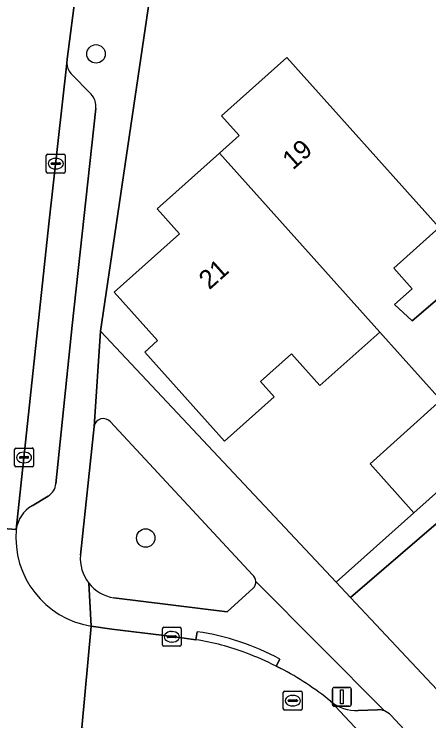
# Model space of a CAD drawing. Extents: x 159960 to 160866, y 382700 to 383354.
# Drawn here: x 160655.44 to 160677.38, y 383036.87 to 383074.27 of the extents above; entities that cross this region are included whole.
import ezdxf

# ---------------------------------------------------------------- set-up
doc = ezdxf.new("R2010")
doc.units = 0
for name, color, linetype in [('IMGEO_Boom', 7, 'Continuous'), ('IMGEO_Erf', 7, 'Continuous'), ('IMGEO_Groenvoorziening', 7, 'Continuous'), ('IMGEO_Kolk', 7, 'Continuous'), ('IMGEO_Lichtmast', 7, 'Continuous'), ('IMGEO_Pand', 7, 'Continuous'), ('IMGEO_Pand_nummerreeks', 7, 'Continuous'), ('IMGEO_Parkeervlak_open', 7, 'Continuous'), ('IMGEO_Rijbaan_lokaal_open', 7, 'Continuous'), ('IMGEO_Rioolput', 7, 'Continuous'), ('IMGEO_Voetpad_open', 7, 'Continuous')]:
    doc.layers.add(name, color=color, linetype=linetype)

msp = doc.modelspace()

# ---------------------------------------------------------------- linework, layer by layer
at = {"layer": 'IMGEO_Boom'}
for centre in [(160659.771, 383072.161), (160662.4, 383046.543)]:
    msp.add_circle(centre, 0.489, dxfattribs=at)
at = {"layer": 'IMGEO_Erf'}
for points in [[(160665.195, 383092.6), (160660.012, 383057.484), (160672.474, 383044.199), (160676.587, 383047.882), (160674.265, 383050.474), (160678.012, 383053.829), (160674.775, 383057.44), (160671.617, 383054.612), (160670.115, 383056.288), (160668.476, 383054.82), (160669.189, 383054.022), (160666.566, 383051.673), (160662.349, 383056.383), (160663.027, 383056.99), (160660.738, 383059.547), (160664.186, 383062.634), (160663.002, 383063.956), (160666.294, 383066.904), (160667.341, 383067.841), (160666.412, 383068.878), (160669.867, 383071.971), (160677.926, 383062.972), (160675.523, 383060.82), (160676.492, 383059.737), (160675.561, 383058.904), (160676.498, 383058.036), (160678.204, 383059.491)], [(160685.814, 383054.228), (160673.235, 383043.388), (160678.604, 383037.664)]]:
    msp.add_lwpolyline(points, dxfattribs=at)
at = {"layer": 'IMGEO_Groenvoorziening'}
for points in [[(160659.666, 383052.443), (160658.945, 383045.641)], [(160668.044, 383044.594), (160660.533, 383052.685)], [(160660.709, 383043.374), (160666.715, 383042.638), (160668.082, 383043.885)]]:
    msp.add_lwpolyline(points, dxfattribs=at)
for centre, radius, start, end in [((160660.155, 383052.367), 0.495, 40.0833, 171.1081), ((160661.047, 383045.459), 2.11, 175.0544, 217.9385), ((160667.751, 383044.223), 0.472, 2.9969, 51.7119), ((160661.055, 383045.466), 2.12, 217.945, 260.6116), ((160667.756, 383044.221), 0.468, 314.1846, 3.3601)]:
    msp.add_arc(centre, radius, start, end, dxfattribs=at)
at = {"layer": 'IMGEO_Kolk'}
for p, q in [((160657.14, 383065.928), (160657.14, 383066.78)), ((160657.215, 383066.854), (160658.067, 383066.854)), ((160657.628, 383066.634), (160657.653, 383066.634)), ((160658.141, 383066.78), (160658.141, 383065.928)), ((160657.399, 383066.348), (160657.399, 383066.36)), ((160657.837, 383066.311), (160657.439, 383066.311)), ((160657.442, 383066.397), (160657.84, 383066.397)), ((160657.883, 383066.36), (160657.883, 383066.348)), ((160658.067, 383065.854), (160657.215, 383065.854)), ((160657.651, 383066.074), (160657.626, 383066.074)), ((160655.462, 383050.38), (160655.462, 383051.232)), ((160655.537, 383051.306), (160656.389, 383051.306)), ((160656.463, 383051.232), (160656.463, 383050.38)), ((160655.764, 383050.849), (160656.162, 383050.849)), ((160655.95, 383051.086), (160655.975, 383051.086)), ((160655.721, 383050.8), (160655.721, 383050.812)), ((160656.159, 383050.763), (160655.761, 383050.763)), ((160655.973, 383050.526), (160655.948, 383050.526)), ((160656.205, 383050.812), (160656.205, 383050.8)), ((160656.389, 383050.306), (160655.537, 383050.306)), ((160663.279, 383040.891), (160663.279, 383041.743)), ((160663.354, 383041.817), (160664.206, 383041.817)), ((160663.767, 383041.597), (160663.792, 383041.597)), ((160664.28, 383041.743), (160664.28, 383040.891)), ((160663.538, 383041.311), (160663.538, 383041.323)), ((160663.976, 383041.274), (160663.578, 383041.274)), ((160663.581, 383041.36), (160663.979, 383041.36)), ((160664.022, 383041.323), (160664.022, 383041.311)), ((160664.206, 383040.817), (160663.354, 383040.817)), ((160663.79, 383041.037), (160663.765, 383041.037))]:
    msp.add_line(p, q, dxfattribs=at)
for points in [[(160657.14, 383065.928), (160657.14, 383066.78)], [(160657.215, 383066.854), (160658.067, 383066.854)], [(160658.141, 383066.78), (160658.141, 383065.928)], [(160658.067, 383065.854), (160657.215, 383065.854)], [(160655.462, 383050.38), (160655.462, 383051.232)], [(160655.537, 383051.306), (160656.389, 383051.306)], [(160656.463, 383051.232), (160656.463, 383050.38)], [(160656.389, 383050.306), (160655.537, 383050.306)], [(160663.279, 383040.891), (160663.279, 383041.743)], [(160663.354, 383041.817), (160664.206, 383041.817)], [(160664.28, 383041.743), (160664.28, 383040.891)], [(160664.206, 383040.817), (160663.354, 383040.817)]]:
    msp.add_lwpolyline(points, dxfattribs=at)
for centre, radius, start, end in [((160657.217, 383066.778), 0.0765, 91.552, 178.448), ((160657.217, 383066.778), 0.0765, 91.552, 178.448), ((160658.065, 383066.778), 0.0765, 1.552, 88.448), ((160658.065, 383066.778), 0.0765, 1.552, 88.448), ((160657.439, 383066.357), 0.0403, 85.8775, 175.7526), ((160657.436, 383066.347), 0.0366, 178.938, 274.7102), ((160657.84, 383066.354), 0.043, 264.8664, 352.4533), ((160657.844, 383066.359), 0.0386, 1.7309, 96.639), ((160657.217, 383065.93), 0.0765, 181.552, 268.448), ((160657.217, 383065.93), 0.0765, 181.552, 268.448), ((160658.065, 383065.93), 0.0765, 271.552, 358.448), ((160658.065, 383065.93), 0.0765, 271.552, 358.448), ((160655.539, 383051.23), 0.0765, 91.552, 178.448), ((160655.539, 383051.23), 0.0765, 91.552, 178.448), ((160656.387, 383051.23), 0.0765, 1.552, 88.448), ((160656.387, 383051.23), 0.0765, 1.552, 88.448), ((160655.761, 383050.809), 0.0403, 85.8775, 175.7526), ((160656.166, 383050.811), 0.0386, 1.7309, 96.639), ((160655.758, 383050.799), 0.0366, 178.938, 274.7102), ((160656.162, 383050.806), 0.043, 264.8664, 352.4533), ((160655.539, 383050.382), 0.0765, 181.552, 268.448), ((160655.539, 383050.382), 0.0765, 181.552, 268.448), ((160656.387, 383050.382), 0.0765, 271.552, 358.448), ((160656.387, 383050.382), 0.0765, 271.552, 358.448), ((160663.356, 383041.741), 0.0765, 91.552, 178.448), ((160663.356, 383041.741), 0.0765, 91.552, 178.448), ((160664.204, 383041.741), 0.0765, 1.552, 88.448), ((160664.204, 383041.741), 0.0765, 1.552, 88.448), ((160663.578, 383041.32), 0.0403, 85.8775, 175.7526), ((160663.575, 383041.31), 0.0366, 178.938, 274.7102), ((160663.979, 383041.317), 0.043, 264.8664, 352.4533), ((160663.983, 383041.322), 0.0386, 1.7309, 96.639), ((160663.356, 383040.893), 0.0765, 181.552, 268.448), ((160663.356, 383040.893), 0.0765, 181.552, 268.448), ((160664.204, 383040.893), 0.0765, 271.552, 358.448), ((160664.204, 383040.893), 0.0765, 271.552, 358.448)]:
    msp.add_arc(centre, radius, start, end, dxfattribs=at)
for centre, major_axis, ratio, start_param, end_param in [((160657.627, 383066.354), (-0.387, 0.002), 0.722429, 4.712389, 7.853982), ((160657.652, 383066.354), (-0.39, 0.002), 0.717154, 1.570796, 4.712389), ((160655.949, 383050.806), (-0.387, 0.002), 0.722429, 4.712389, 7.853982), ((160655.974, 383050.806), (-0.39, 0.002), 0.717154, 1.570796, 4.712389), ((160663.766, 383041.317), (-0.387, 0.002), 0.722429, 4.712389, 7.853982), ((160663.791, 383041.317), (-0.39, 0.002), 0.717154, 1.570796, 4.712389)]:
    msp.add_ellipse(centre, major_axis=major_axis, ratio=ratio, start_param=start_param, end_param=end_param, dxfattribs=at)
at = {"layer": 'IMGEO_Lichtmast'}
for p, q in [((160672.278, 383037.738), (160672.278, 383038.538)), ((160672.278, 383038.538), (160672.278, 383037.738)), ((160672.378, 383038.638), (160673.168, 383038.638)), ((160673.168, 383038.638), (160672.378, 383038.638)), ((160673.268, 383038.538), (160673.268, 383037.738)), ((160673.268, 383037.738), (160673.268, 383038.538)), ((160673.168, 383037.638), (160672.378, 383037.638)), ((160672.378, 383037.638), (160673.168, 383037.638))]:
    msp.add_line(p, q, dxfattribs=at)
msp.add_lwpolyline([(160672.698, 383038.513), (160672.848, 383038.513), (160672.848, 383037.763), (160672.698, 383037.763), (160672.698, 383038.513)], dxfattribs=at)
for centre, start, end in [((160672.378, 383038.538), 90, 180), ((160672.378, 383038.538), 90, 180), ((160673.168, 383038.538), 0, 90), ((160673.168, 383038.538), 360, 90), ((160672.378, 383037.738), 180, 270), ((160672.378, 383037.738), 180, 270), ((160673.168, 383037.738), 270, 0), ((160673.168, 383037.738), 270, 0)]:
    msp.add_arc(centre, 0.1, start, end, dxfattribs=at)
at = {"layer": 'IMGEO_Pand'}
for points in [[(160677.926, 383062.972), (160669.867, 383071.971), (160666.412, 383068.878), (160667.341, 383067.841), (160666.294, 383066.904), (160674.775, 383057.44), (160678.012, 383053.829), (160680.312, 383051.218), (160683.414, 383053.647), (160683.334, 383053.737), (160678.204, 383059.491), (160676.498, 383058.036), (160675.561, 383058.904), (160676.492, 383059.737), (160675.523, 383060.82)], [(160674.775, 383057.44), (160666.294, 383066.904), (160663.002, 383063.956), (160664.186, 383062.634), (160660.738, 383059.547), (160663.027, 383056.99), (160662.349, 383056.383), (160666.566, 383051.673), (160669.189, 383054.022), (160668.476, 383054.82), (160670.115, 383056.288), (160671.617, 383054.612)], [(160678.012, 383053.829), (160674.265, 383050.474), (160676.587, 383047.882), (160680.312, 383051.218)]]:
    msp.add_lwpolyline(points, close=True, dxfattribs=at)
at = {"layer": 'IMGEO_Parkeervlak_open'}
for points in [[(160658.227, 383071.676), (160657.282, 383063.173), (160655.553, 383046.99)], [(160659.508, 383070.035), (160658.432, 383071.123)], [(160657.651, 383049.415), (160658.514, 383057.796), (160659.756, 383069.266)], [(160656.389, 383048.245), (160657.247, 383048.766)], [(160672.178, 383037.909), (160700.852, 383007.229), (160702.135, 383008.415), (160675.357, 383037.17)], [(160674.654, 383037.459), (160673.636, 383037.411)]]:
    msp.add_lwpolyline(points, dxfattribs=at)
for centre, radius, start, end in [((160659.091, 383071.682), 0.864, 180.374, 220.306), ((160658.795, 383069.381), 0.968, 353.1932, 42.5555), ((160656.718, 383049.545), 0.942, 304.1579, 352.0379), ((160657.2, 383046.799), 1.658, 119.2774, 173.3846), ((160673.556, 383039.561), 2.152, 230.1639, 272.1195), ((160674.691, 383036.541), 0.919, 67.8656, 92.2892), ((160674.684, 383036.541), 0.922, 43.0508, 67.4473)]:
    msp.add_arc(centre, radius, start, end, dxfattribs=at)
at = {"layer": 'IMGEO_Rijbaan_lokaal_open'}
msp.add_lwpolyline([(160659.494, 383080.886), (160660.041, 383084.605), (160660.498, 383087.616), (160660.926, 383089.368), (160661.241, 383090.564), (160657.352, 383091.131), (160657.323, 383090.965), (160655.415, 383078.027), (160654.738, 383073.061), (160652.03, 383047.251), (160655.553, 383046.99), (160657.282, 383063.173), (160658.227, 383071.676), (160658.25, 383071.882), (160658.716, 383075.567), (160659.258, 383079.296), (160659.36, 383080.034)], close=True, dxfattribs=at)
for points in [[(160655.553, 383046.99), (160652.03, 383047.251), (160651.524, 383047.306), (160651.359, 383045.742), (160650.909, 383041.465), (160650.648, 383038.987), (160650.186, 383034.604), (160650, 383032.838), (160653.531, 383032.462)], [(160659.022, 383036.49), (160659.516, 383041.884)], [(160665.058, 383041.161), (160663.814, 383041.323), (160660.601, 383041.727), (160659.516, 383041.884), (160659.022, 383036.49), (160659.221, 383036.467), (160669.375, 383035.313)], [(160669.54, 383039.643), (160669.292, 383039.757)], [(160670.275, 383034.824), (160698.234, 383004.765), (160700.852, 383007.229), (160672.178, 383037.909)]]:
    msp.add_lwpolyline(points, dxfattribs=at)
for centre, radius, start, end in [((160660.265, 383046.557), 4.732, 174.7443, 260.889), ((160662.844, 383027.415), 13.923, 69.4837, 80.8515), ((160662.841, 383027.375), 13.962, 62.4796, 69.5276), ((160662.174, 383025.564), 15.89, 50.9814, 62.3834)]:
    msp.add_arc(centre, radius, start, end, dxfattribs=at)
at = {"layer": 'IMGEO_Rioolput'}
for p, q in [((160669.677, 383037.509), (160669.677, 383038.361)), ((160669.752, 383038.435), (160670.604, 383038.435)), ((160670.165, 383038.215), (160670.19, 383038.215)), ((160670.678, 383038.361), (160670.678, 383037.509)), ((160669.936, 383037.929), (160669.936, 383037.941)), ((160670.374, 383037.892), (160669.976, 383037.892)), ((160669.979, 383037.978), (160670.377, 383037.978)), ((160670.42, 383037.941), (160670.42, 383037.929)), ((160670.604, 383037.435), (160669.752, 383037.435)), ((160670.188, 383037.655), (160670.163, 383037.655))]:
    msp.add_line(p, q, dxfattribs=at)
for points in [[(160669.677, 383037.509), (160669.677, 383038.361)], [(160669.752, 383038.435), (160670.604, 383038.435)], [(160670.678, 383038.361), (160670.678, 383037.509)], [(160670.604, 383037.435), (160669.752, 383037.435)]]:
    msp.add_lwpolyline(points, dxfattribs=at)
for centre, radius, start, end in [((160669.754, 383038.359), 0.0765, 91.552, 178.448), ((160669.754, 383038.359), 0.0765, 91.552, 178.448), ((160670.602, 383038.359), 0.0765, 1.552, 88.448), ((160670.602, 383038.359), 0.0765, 1.552, 88.448), ((160669.976, 383037.938), 0.0403, 85.8775, 175.7526), ((160669.973, 383037.928), 0.0366, 178.938, 274.7102), ((160670.377, 383037.935), 0.043, 264.8664, 352.4533), ((160670.381, 383037.94), 0.0386, 1.7309, 96.639), ((160669.754, 383037.511), 0.0765, 181.552, 268.448), ((160669.754, 383037.511), 0.0765, 181.552, 268.448), ((160670.602, 383037.511), 0.0765, 271.552, 358.448), ((160670.602, 383037.511), 0.0765, 271.552, 358.448)]:
    msp.add_arc(centre, radius, start, end, dxfattribs=at)
for centre, major_axis, ratio, start_param, end_param in [((160670.164, 383037.935), (-0.387, 0.002), 0.722429, 4.712389, 7.853982), ((160670.189, 383037.935), (-0.39, 0.002), 0.717154, 1.570796, 4.712389)]:
    msp.add_ellipse(centre, major_axis=major_axis, ratio=ratio, start_param=start_param, end_param=end_param, dxfattribs=at)
at = {"layer": 'IMGEO_Voetpad_open'}
for points in [[(160662.001, 383093.445), (160661.241, 383090.564), (160660.926, 383089.368), (160660.498, 383087.616), (160660.041, 383084.605), (160660.485, 383084.553), (160659.929, 383080.811), (160659.494, 383080.886), (160659.36, 383080.034), (160659.258, 383079.296), (160659.698, 383079.245), (160659.169, 383075.526), (160658.716, 383075.567), (160658.25, 383071.882), (160658.227, 383071.676)], [(160658.945, 383045.641), (160659.666, 383052.443), (160660.012, 383057.484), (160665.195, 383092.6)], [(160658.432, 383071.123), (160659.508, 383070.035)], [(160659.756, 383069.266), (160658.514, 383057.796), (160657.651, 383049.415)], [(160660.012, 383057.484), (160659.666, 383052.443)], [(160678.604, 383037.664), (160673.235, 383043.388), (160672.474, 383044.199), (160660.012, 383057.484)], [(160660.533, 383052.685), (160668.044, 383044.594)], [(160657.247, 383048.766), (160656.389, 383048.245)], [(160659.383, 383044.162), (160659.516, 383041.884), (160660.601, 383041.727), (160663.814, 383041.323), (160665.058, 383041.161), (160665.128, 383041.58)], [(160659.516, 383041.884), (160659.383, 383044.162)], [(160675.037, 383037.392), (160668.223, 383044.248)], [(160668.223, 383044.248), (160675.037, 383037.392)], [(160668.082, 383043.885), (160666.715, 383042.638), (160660.709, 383043.374)], [(160665.128, 383041.58), (160665.058, 383041.161)], [(160669.499, 383040.132), (160669.292, 383039.757), (160669.54, 383039.643)], [(160669.292, 383039.757), (160669.499, 383040.132)], [(160673.636, 383037.411), (160674.654, 383037.459)], [(160675.357, 383037.17), (160702.135, 383008.415)]]:
    msp.add_lwpolyline(points, dxfattribs=at)
msp.add_lwpolyline([(160683.334, 383053.737), (160683.414, 383053.647), (160680.312, 383051.218), (160676.587, 383047.882), (160672.474, 383044.199), (160673.235, 383043.388), (160685.814, 383054.228), (160684.932, 383055.195)], close=True, dxfattribs=at)
for centre, radius, start, end in [((160659.091, 383071.682), 0.864, 180.374, 220.306), ((160658.795, 383069.381), 0.968, 353.1932, 42.5555), ((160660.155, 383052.367), 0.495, 40.0833, 171.1081), ((160656.718, 383049.545), 0.942, 304.1579, 352.0379), ((160657.2, 383046.799), 1.658, 119.2774, 173.3846), ((160660.265, 383046.557), 4.732, 174.7443, 260.889), ((160661.047, 383045.459), 2.11, 175.0544, 217.9385), ((160667.751, 383044.223), 0.472, 2.9969, 51.7119), ((160661.055, 383045.466), 2.12, 217.945, 260.6116), ((160667.756, 383044.221), 0.468, 314.1846, 3.3601), ((160663.289, 383028.709), 13.002, 61.4719, 81.8707), ((160663.289, 383028.709), 13.002, 61.4719, 81.8707), ((160662.844, 383027.415), 13.923, 69.4837, 80.8515), ((160662.841, 383027.375), 13.962, 62.4796, 69.5276), ((160662.174, 383025.564), 15.89, 50.9814, 62.3834), ((160673.556, 383039.561), 2.152, 230.1639, 272.1195), ((160674.691, 383036.541), 0.919, 67.8656, 92.2892), ((160674.684, 383036.541), 0.922, 43.0508, 67.4473)]:
    msp.add_arc(centre, radius, start, end, dxfattribs=at)

# ---------------------------------------------------------------- texts
at = {"layer": 'IMGEO_Pand_nummerreeks'}
for s, rotation, p in [('19', 41.8374, (160670.185, 383065.984)), ('21', 41.8381, (160665.765, 383059.645))]:
    msp.add_text(s, height=1, rotation=rotation, dxfattribs=at).set_placement(p)

doc.saveas('drawing.dxf')
